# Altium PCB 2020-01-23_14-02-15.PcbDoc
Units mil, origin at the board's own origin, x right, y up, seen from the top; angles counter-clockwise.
Board outline 2000 x 2400 mil, 4 copper layers (Top Layer, MidLayer1, MidLayer2, Bottom Layer); 15 components, 7 nets, 30 pads, 23 vias.
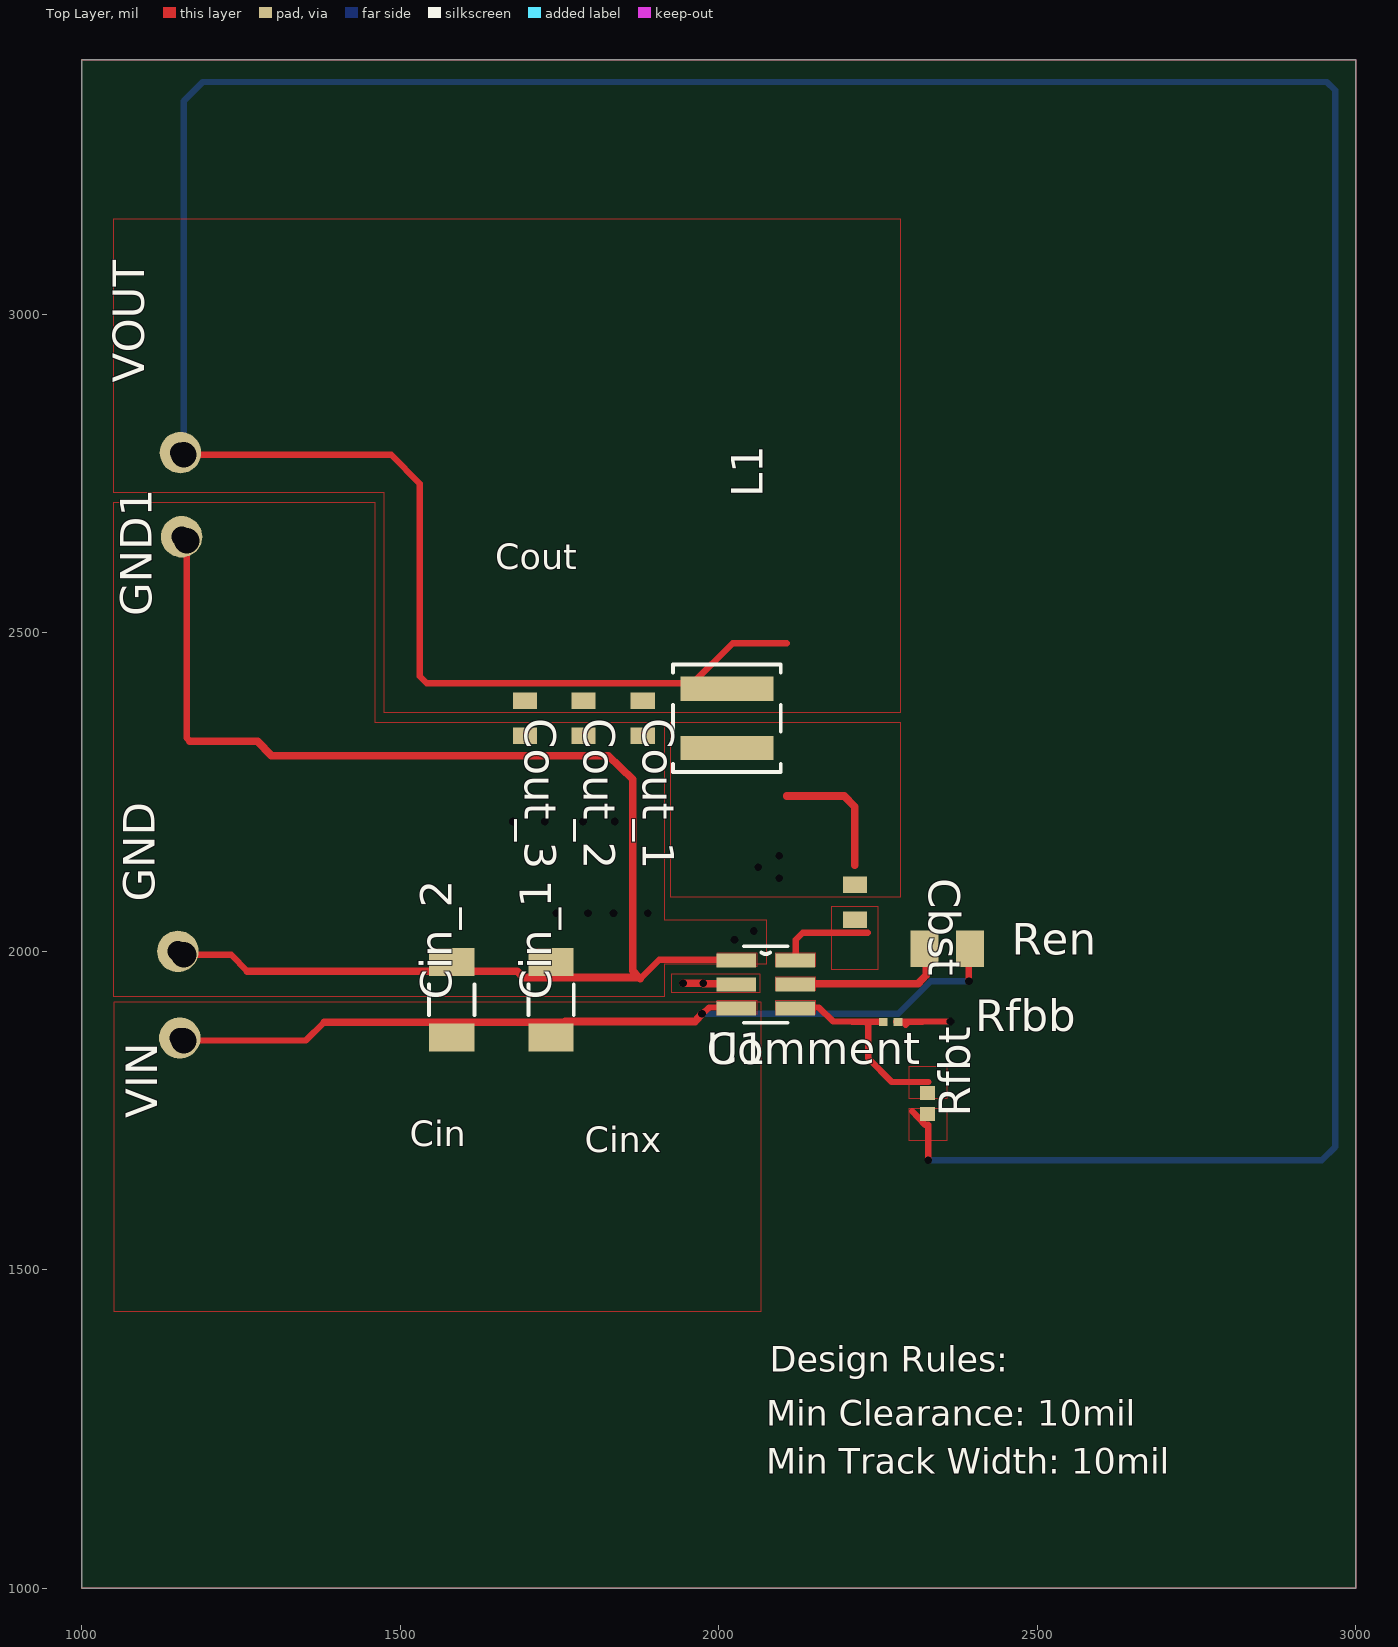
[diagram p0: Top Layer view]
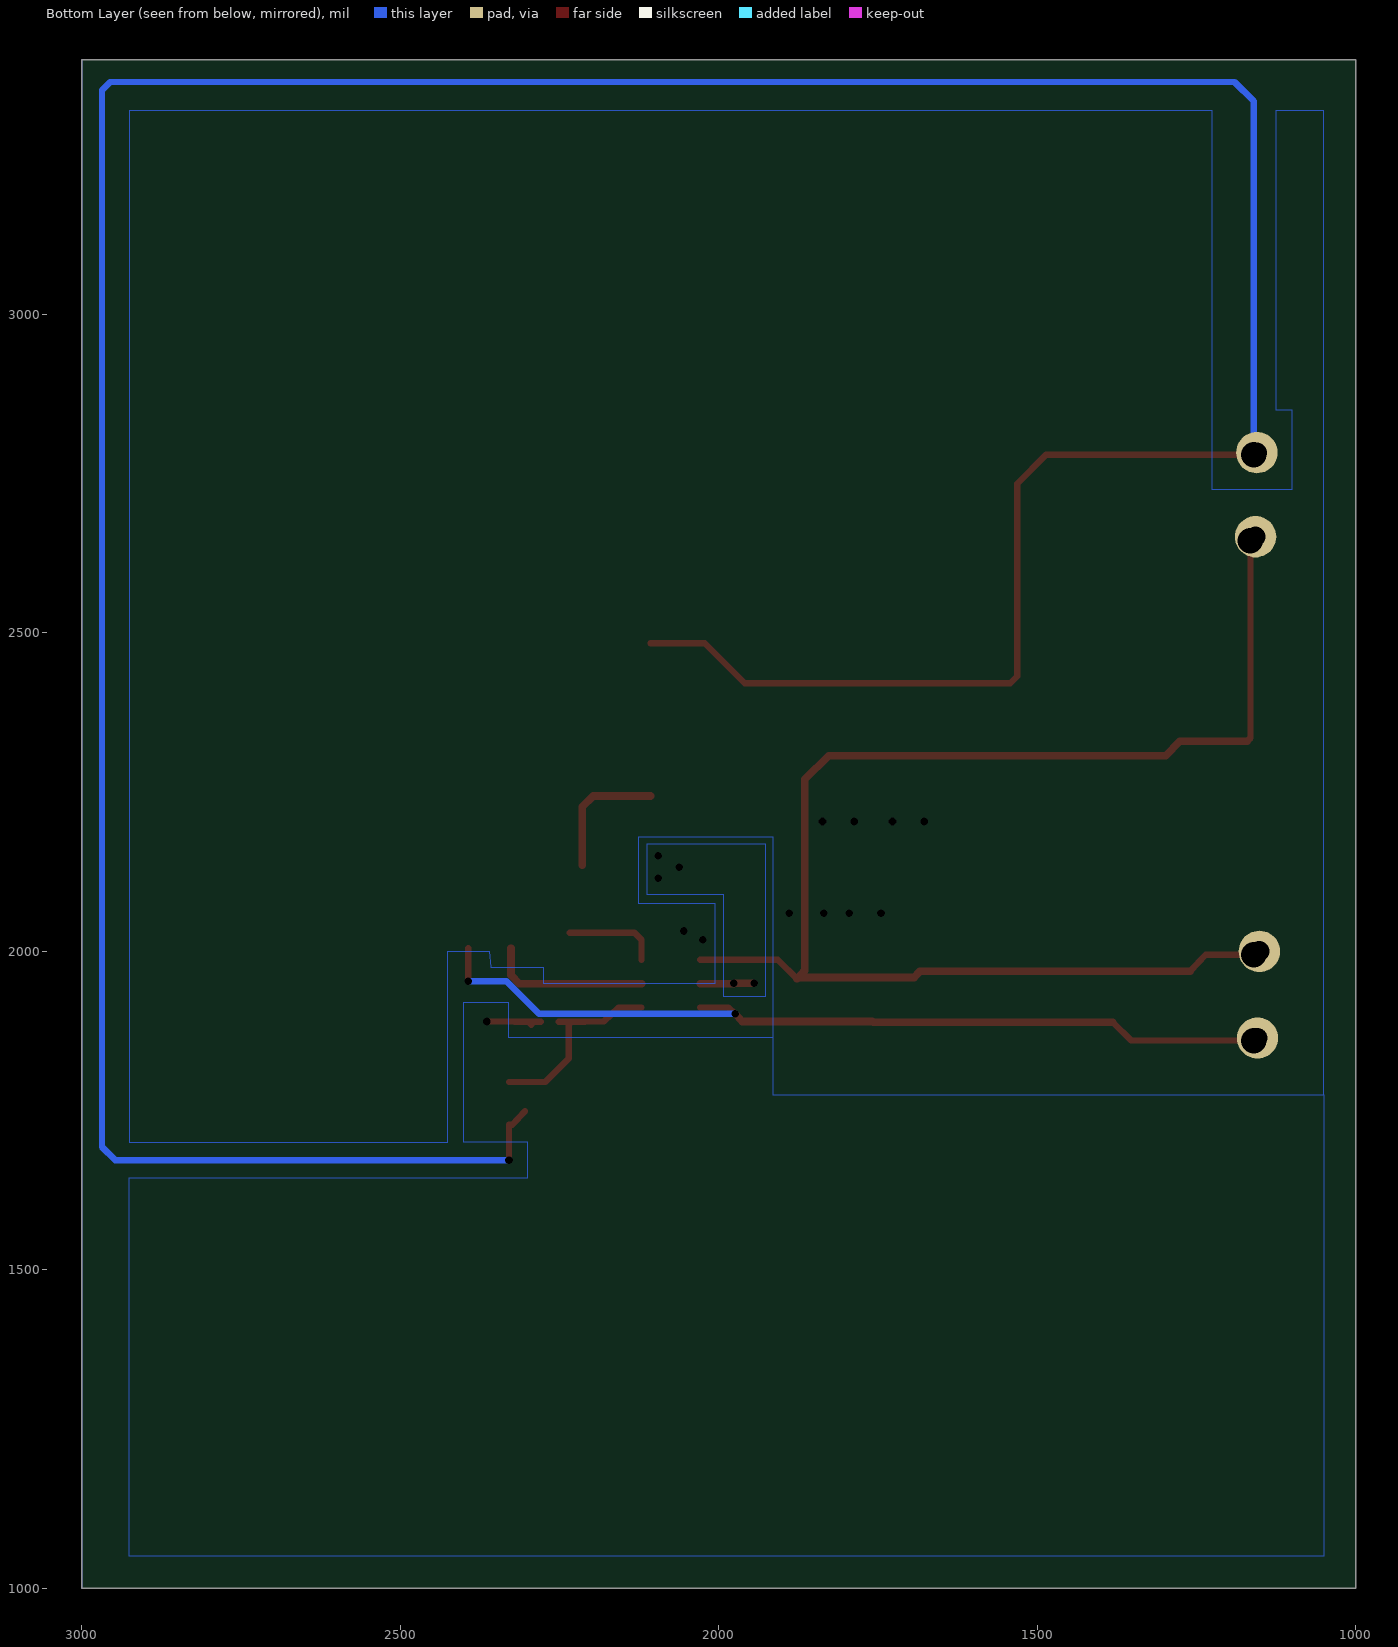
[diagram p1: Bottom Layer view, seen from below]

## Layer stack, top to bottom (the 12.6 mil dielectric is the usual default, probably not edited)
Top Layer: signal copper 1.4
Dielectric: core 12.6, FR-4, Dk 4.8
MidLayer1: signal copper 1.4
Dielectric: prepreg 12.6, FR-4, Dk 4.8
MidLayer2: signal copper 1.4
Dielectric: core 12.6, FR-4, Dk 4.8
Bottom Layer: signal copper 1.4

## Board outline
1000,1000 3000,1000 3000,3400 1000,3400

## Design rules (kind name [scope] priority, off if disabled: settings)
PlaneConnect [All] p0: scope1count=1 scope1_0_kind=Board scope1_0_value=Board scope2count=1 scope2_0_kind=Board scope2_0_value=Board commentlength=0 planeconnectstyle=Direct reliefexpansion=20 reliefentries=4 reliefconductorwidth=10 reliefairgap=10
PlaneConnect [All] p1: planeconnectstyle=Direct reliefexpansion=20 reliefentries=4 reliefconductorwidth=10 reliefairgap=10
PolygonConnect [All] p0: scope1count=1 scope1_0_kind=Board scope1_0_value=Board scope2count=1 scope2_0_kind=Board scope2_0_value=Board commentlength=0 connectstyle=Direct reliefconductorwidth=10 reliefentries=4 polygonreliefangle="90 Angle"
PolygonConnect [All] p1: connectstyle=Direct reliefconductorwidth=10 reliefentries=4 polygonreliefangle="90 Angle"

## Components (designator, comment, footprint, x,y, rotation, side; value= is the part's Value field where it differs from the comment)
Cbst "" 0603 2214,2077 r270 top
Cin_1 "" 1206_190 1737,1924 r90 top
Cin_2 "" 1206_190 1581,1924 r90 top
Cout_1 "" 0603 1881,2366 r270 top
Cout_2 "" 0603 1788,2366 r270 top
Cout_3 "" 0603 1696,2366 r270 top
GND "" TP-1502 1151,2000 r90 top
GND1 "" TP-1502 1157,2651 r90 top
L1 "" XAL4030 2013,2366 r90 top
Ren "" 0805 2359,2004 r0 top
Rfbb "" 0201 2270,1889 r0 top
Rfbt "" 0402 2328,1761 r90 top
U1 "" DDC0006A 2074,1948 r0 top
VIN "" TP-1502 1154,1864 r90 top
VOUT "" TP-1502 1155,2783 r90 top

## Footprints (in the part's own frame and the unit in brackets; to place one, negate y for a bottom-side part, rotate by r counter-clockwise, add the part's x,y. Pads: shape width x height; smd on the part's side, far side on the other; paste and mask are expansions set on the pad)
0201 [mil]
  rect 14x13 smd: 1(-11.5,0) 2(11.5,0)
0402 [mil]
  rect 22x24 smd: 1(-16.5,0) 2(16.5,0)
0603 [mil]
  rect 26x38 smd: 1(-27.5,0) 2(27.5,0)
0805 [mil]
  rect 44x57 smd: 1(-35.5,0) 2(35.5,0)
1206_190 [mil]
  rect 44x71 smd: 1(-59,0) 2(59,0)
  silkscreen extent -24,-36 24,36
DDC0006A [mil]
  rect 62x22 smd: 1(-46,37.4) 2(-46,0) 3(-46,-37.4) 4(46,-37.4) 5(46,0) 6(46,37.4)
  silkscreen extent -34,-60 34,60
TP-1502 [mil]
  round 65 / inner round 0 / far side round 65 hole 32: 1(0,0)
XAL4030 [mil]
  rect 38x146 smd: 1(-46.5,0) 2(46.5,0)
  silkscreen extent -84,-84 84,84

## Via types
v1: diameter 0, hole 12, Top Layer to Bottom Layer, 19 vias
v2: diameter 0, hole 40, Top Layer to Bottom Layer, 4 vias

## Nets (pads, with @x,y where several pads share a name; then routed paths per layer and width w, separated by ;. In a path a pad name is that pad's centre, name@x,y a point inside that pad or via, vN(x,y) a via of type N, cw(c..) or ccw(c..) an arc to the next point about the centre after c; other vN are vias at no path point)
0: Cin_1.2 Cin_2.2 Cout_1.2 Cout_2.2 Cout_3.2 GND1.1 GND.1 Rfbb.2 U1.1 | length 2362.7
  Top Layer w10: v2(1160,1995) 1235,1995 1260,1969 ; v2(1165,2645) 1165,2335 1170,2330 ; 1877,1957 1907,1987 U1.1@2029,1987 ; Rfbb.2@2279,1889.5 2320,1889.5 ; 2294,1885 2299,1890 v1(2364,1890)
  Top Layer w12: 1170,2330 1276,2330 1298,2307 1727,2307 1827,2307 1865,2270 1865,1970 1875,1959 ; 1260,1969 1684,1969 1693,1959 1875,1959 ; 1877,1957 1875,1959
  other v1: 2025,2018 2055,2032 1745,2060 1795,2060 1835,2060 1889,2060 1677,2204 1727,2204 1787,2204 1837,2204
2: Cin_1.1 Cin_2.1 Ren.2 U1.3 VIN.1 | length 1382.5
  Top Layer w10: v2(1160,1860) 1352,1860 1381,1889 ; v1(1974,1902) 1985,1912 U1.3@2029,1912 ; v1(2393,1953) Ren.2@2393,2005
  Top Layer w12: 1381,1889 1757,1889 1759,1890 1963,1890 v1(1974,1902)
  Bottom Layer w10: v1(1974,1902) 2282,1902 2333,1953 v1(2393,1953)
5: Rfbb.1 Rfbt.2 U1.4 | length 328.2
  Top Layer w10: U1.4@2121,1912 2157,1912 2180,1890 2231,1890 2231,1889 ; 2210,1889.5 2251,1889.5 ; 2235,1890 2235,1832 2272,1795 2329,1795
8: Cbst.1 L1.1 U1.2 | length 292
  Top Layer w12: v1(1944,1950) v1(1976,1950) 1976,1949 U1.2@2029,1949 ; 2107,2244 2197,2244 2214,2227 2214,2135
  other v1: 2095,2115 2062,2132 2095,2150
9: Cout_1.1 Cout_2.1 Cout_3.1 L1.2 Rfbt.1 VOUT.1 | length 6076.5
  Top Layer w10: v2(1160,2780) 1486,2780 1531,2734 1531,2432 1542,2421 1727,2421 1959,2421 2022,2484 2107,2484 ; 2304,1749 2324,1728 2329,1728 v1(2329,1672)
  Bottom Layer w10: v2(1160,2780) 1160,3335 1190,3365 2955,3365 2968,3352 2968,1693 2947,1672 v1(2329,1672)
13: Cbst.2 U1.6 | length 148.6
  Top Layer w10: U1.6@2121,1987 2121,2018 2132,2029 2234,2029
17: Ren.1 U1.5 | length 253.1
  Top Layer w12: U1.5@2121,1949 2313,1949 2326,1963 Ren.1@2326,2005

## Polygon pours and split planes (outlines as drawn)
8 on Bottom Layer " " (solid, pour order 11): 1927,1929 1992,1929 1992,2089 2112,2089 2112,2169 1927,2169
0 on Bottom Layer " " (solid, pour order 14): 1050,1775 1050,1050 2925,1050 2925,1645 2300,1645 2300,1700 2400,1700 2400,1920 2330,1920 2330,1865 1915,1865 1915,1775
0 on Bottom Layer " " (solid, pour order 15): 1050,3320 1125,3320 1125,2850 1100,2850 1100,2725 1225,2725 1225,3320 2925,3320 2925,1700 2425,1700 2425,2000 2360,2000 2358,1975 2275,1975 2275,1950 2005,1950 2005,2075 2125,2075 2125,2180 1915,2180 1915,1775 1050,1775
13 on Top Layer " " (solid, pour order 0): 2178,1971 2178,2071 2250,2071 2250,1971
5 on Top Layer " " (solid, pour order 1): 2299,1769 2299,1820 2358,1820 2358,1769
9 on Top Layer " " (solid, pour order 2): 2299,1703 2299,1754 2358,1754 2358,1703
13 on Top Layer " " (solid, pour order 3): 2090,1976 2090,1998 2152,1998 2152,1976
5 on Top Layer " " (solid, pour order 4): 2090,1901 2090,1923 2152,1923 2152,1901
2 on Top Layer " " (solid, pour order 5): 1998,1901 1998,1923 2060,1923 2060,1901
17 on Top Layer " " (solid, pour order 6): 2090,1938 2090,1960 2152,1960 2152,1938
8 on Top Layer " " (solid, pour order 7): 1925,2360 2285,2360 2285,2085 1925,2085
2 on Top Layer " " (solid, pour order 8): 2067,1920 1050,1920 1050,1435 2067,1435
8 on Top Layer " " (solid, pour order 9): 2065,1936 2065,1964 1995,1964 1926,1964 1926,1936 1995,1936
9 on Top Layer " " (solid, pour order 10): 2285,2375 1475,2375 1475,2720 1050,2720 1050,3150 2285,3150
0 on Top Layer " " (solid, pour order 12): 1998,1976 1998,1998 2060,1998 2060,1976
0 on Top Layer " " (solid, pour order 13): 2075,1980 1915,1980 1915,1929 1050,1929 1050,2705 1460,2705 1460,2360 1915,2360 1915,2050 2075,2050

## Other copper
Multi-Layer:
  the board outline again, w1

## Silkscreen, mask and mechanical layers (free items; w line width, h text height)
Top Overlay:
  text "Cout" at 1649,2600 h40
  text "Cin" at 1515,1694 h40
  text "Cinx" at 1790,1685 h40
  text "Design Rules:" at 2080,1340 h40
  text "Min Clearance: 10mil" at 2075,1255 h40
  text "Min Track Width: 10mil" at 2075,1180 h40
